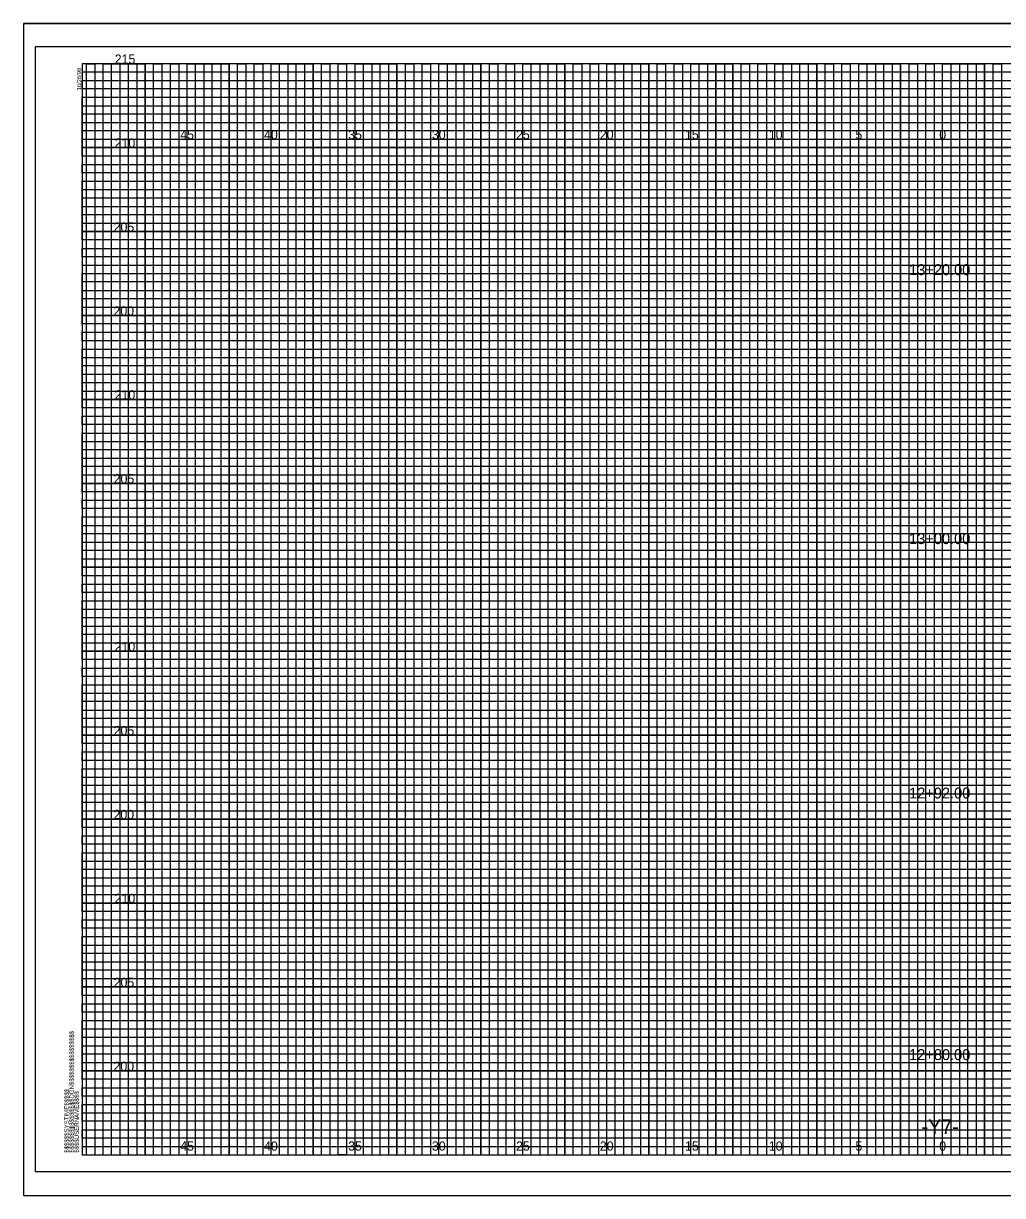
# Model space of a CAD drawing. Extents: x -4 to 103, y -2 to 351.
# Drawn here: x -3.5 to 54.8, y 210.1 to 279.9 of the extents above; entities that cross this region are included whole.
import ezdxf

# ---------------------------------------------------------------- set-up
doc = ezdxf.new("R2010")
doc.units = 0
for name, color, linetype in [('Exist XS Ground Line', 7, 'Continuous'), ('Old_Level_10', 7, 'Continuous'), ('Old_Level_16', 7, 'Continuous'), ('Old_Level_3', 7, 'Continuous'), ('Old_Level_4', 7, 'Continuous'), ('Old_Level_5', 7, 'Continuous'), ('Old_Level_6', 7, 'Continuous'), ('Old_Level_8', 7, 'Continuous'), ('Prop XS Finish Grade', 7, 'Continuous'), ('Prop XS SE Text', 7, 'Continuous'), ('Prop XS Subgrade Earthwork', 7, 'Continuous')]:
    doc.layers.add(name, color=color, linetype=linetype)

msp = doc.modelspace()

# ---------------------------------------------------------------- linework, layer by layer
at = {"layer": 'Old_Level_10'}
for p, q in [((1.25, 212.475), (1.25, 277.475)), ((3.75, 212.475), (3.75, 277.475)), ((6.25, 212.475), (6.25, 277.475)), ((8.75, 212.475), (8.75, 277.475)), ((11.25, 212.475), (11.25, 277.475)), ((13.75, 212.475), (13.75, 277.475)), ((16.25, 212.475), (16.25, 277.475)), ((18.75, 212.475), (18.75, 277.475)), ((21.25, 212.475), (21.25, 277.475)), ((23.75, 212.475), (23.75, 277.475)), ((26.25, 212.475), (26.25, 277.475)), ((28.75, 212.475), (28.75, 277.475)), ((31.25, 212.475), (31.25, 277.475)), ((33.75, 212.475), (33.75, 277.475)), ((36.25, 212.475), (36.25, 277.475)), ((38.75, 212.475), (38.75, 277.475)), ((41.25, 212.475), (41.25, 277.475)), ((43.75, 212.475), (43.75, 277.475)), ((46.25, 212.475), (46.25, 277.475)), ((48.75, 212.475), (48.75, 277.475)), ((51.25, 212.475), (51.25, 277.475)), ((53.75, 212.475), (53.75, 277.475)), ((0, 274.975), (74.25, 274.975)), ((0, 272.475), (102.5, 272.475)), ((0, 269.975), (102.5, 269.975)), ((0, 267.475), (102.5, 267.475)), ((0, 264.975), (102.5, 264.975)), ((0, 262.475), (102.5, 262.475)), ((0, 259.975), (102.5, 259.975)), ((0, 257.475), (102.5, 257.475)), ((0, 254.975), (102.5, 254.975)), ((0, 252.475), (102.5, 252.475)), ((0, 249.975), (102.5, 249.975)), ((0, 247.475), (102.5, 247.475)), ((0, 244.975), (102.5, 244.975)), ((0, 242.475), (102.5, 242.475)), ((0, 239.975), (102.5, 239.975)), ((0, 237.475), (102.5, 237.475)), ((0, 234.975), (102.5, 234.975)), ((0, 232.475), (102.5, 232.475)), ((0, 229.975), (102.5, 229.975)), ((0, 227.475), (102.5, 227.475)), ((0, 224.975), (102.5, 224.975)), ((0, 222.475), (102.5, 222.475)), ((0, 219.975), (102.5, 219.975)), ((0, 217.475), (102.5, 217.475)), ((0, 214.975), (102.5, 214.975))]:
    msp.add_line(p, q, dxfattribs=at)
at = {"layer": 'Old_Level_3'}
for p, q in [((-3.5, 279.875), (103.4, 279.875)), ((-3.5, 279.875), (-3.5, 210.05)), ((-3.5, 210.05), (102.1625, 210.05))]:
    msp.add_line(p, q, dxfattribs=at)
at = {"layer": 'Old_Level_4'}
for points in [[(0.25, 212.475), (0.25, 277.475), (0.75, 277.475), (0.75, 212.475), (1.75, 212.475), (1.75, 277.475), (2.25, 277.475), (2.25, 212.475), (2.75, 212.475), (2.75, 277.475), (3.25, 277.475), (3.25, 212.475), (4.25, 212.475), (4.25, 277.475), (4.75, 277.475), (4.75, 212.475), (5.25, 212.475), (5.25, 277.475), (5.75, 277.475), (5.75, 212.475), (6.75, 212.475), (6.75, 277.475), (7.25, 277.475), (7.25, 212.475), (7.75, 212.475), (7.75, 277.475), (8.25, 277.475), (8.25, 212.475), (9.25, 212.475), (9.25, 277.475), (9.75, 277.475), (9.75, 212.475), (10.25, 212.475), (10.25, 277.475), (10.75, 277.475), (10.75, 212.475), (11.75, 212.475), (11.75, 277.475), (12.25, 277.475), (12.25, 212.475), (12.75, 212.475), (12.75, 277.475), (13.25, 277.475), (13.25, 212.475), (14.25, 212.475), (14.25, 277.475), (14.75, 277.475), (14.75, 212.475), (15.75, 212.475), (15.25, 212.475), (15.25, 277.475), (15.75, 277.475), (15.75, 212.475), (16.75, 212.475), (16.75, 277.475), (17.25, 277.475), (17.25, 212.475), (17.75, 212.475), (17.75, 277.475), (18.25, 277.475), (18.25, 212.475), (19.25, 212.475), (19.25, 277.475), (19.75, 277.475), (19.75, 212.475), (20.25, 212.475), (20.25, 277.475), (20.75, 277.475), (20.75, 212.475), (21.75, 212.475), (21.75, 277.475), (22.25, 277.475), (22.25, 212.475), (22.75, 212.475), (22.75, 277.475), (23.25, 277.475), (23.25, 212.475), (24.25, 212.475), (24.25, 277.475), (24.75, 277.475), (24.75, 212.475), (25.25, 212.475), (25.25, 277.475), (25.75, 277.475), (25.75, 212.475), (26.75, 212.475), (26.75, 277.475), (27.25, 277.475), (27.25, 212.475), (27.75, 212.475), (27.75, 277.475), (28.25, 277.475), (28.25, 212.475), (29.25, 212.475), (29.25, 277.475), (29.75, 277.475), (29.75, 212.475), (30.25, 212.475), (30.25, 277.475), (30.75, 277.475), (30.75, 212.475)], [(30.75, 212.475), (31.75, 212.475), (31.75, 277.475), (32.25, 277.475), (32.25, 212.475), (32.75, 212.475), (32.75, 277.475), (33.25, 277.475), (33.25, 212.475), (34.25, 212.475), (34.25, 277.475), (34.75, 277.475), (34.75, 212.475), (35.25, 212.475), (35.25, 277.475), (35.75, 277.475), (35.75, 212.475), (36.75, 212.475), (36.75, 277.475), (37.25, 277.475), (37.25, 212.475), (37.75, 212.475), (37.75, 277.475), (37.75, 212.475)], [(38.25, 277.475), (38.25, 212.475), (39.25, 212.475), (39.25, 277.475), (39.75, 277.475), (39.75, 212.475), (40.25, 212.475), (40.25, 277.475), (40.75, 277.475), (40.75, 212.475), (41.75, 212.475), (41.75, 277.475), (42.25, 277.475), (42.25, 212.475), (42.75, 212.475), (42.75, 277.475), (43.25, 277.475), (43.25, 212.475), (43.75, 212.475), (44.25, 212.475), (44.25, 277.475), (44.75, 277.475), (44.75, 212.475), (45.25, 212.475), (45.25, 277.475), (45.75, 277.475), (45.75, 212.475), (46.75, 212.475), (46.75, 277.475), (47.25, 277.475), (47.25, 212.475), (47.75, 212.475), (47.75, 277.475), (48.25, 277.475), (48.25, 212.475), (49.25, 212.475), (49.25, 277.475), (49.75, 277.475), (49.75, 212.475), (50.25, 212.475), (50.25, 277.475), (50.75, 277.475), (50.75, 212.475), (51.75, 212.475), (51.75, 277.475), (52.25, 277.475), (52.25, 212.475), (52.75, 212.475), (52.75, 277.475), (53.25, 277.475), (53.25, 212.475), (54.25, 212.475), (54.25, 277.475), (54.75, 277.475), (54.75, 212.475), (55.25, 212.475)], [(0, 274.475), (0, 275.475), (74.25, 275.475), (74.25, 275.975), (0, 275.975), (0, 276.475), (74.25, 276.475), (74.25, 276.975), (0, 276.975)], [(102.5, 274.475), (0, 274.475)], [(102.5, 273.475), (0, 273.475), (0, 273.975), (102.5, 273.975)], [(102.5, 271.975), (0, 271.975), (0, 272.975), (102.5, 272.975)], [(102.5, 270.975), (0, 270.975), (0, 271.475), (102.5, 271.475)], [(102.5, 269.475), (0, 269.475), (0, 270.475), (102.5, 270.475)], [(102.5, 268.475), (0, 268.475), (0, 268.975), (102.5, 268.975)], [(102.5, 266.975), (0, 266.975), (0, 267.975), (102.5, 267.975)], [(102.5, 265.975), (0, 265.975), (0, 266.475), (102.5, 266.475)], [(0, 265.475), (102.5, 265.475)], [(102.5, 264.475), (0, 264.475)], [(102.5, 263.475), (0, 263.475), (0, 263.975), (102.5, 263.975)], [(102.5, 261.975), (0, 261.975), (0, 262.975), (102.5, 262.975)], [(102.5, 260.975), (0, 260.975), (0, 261.475), (102.5, 261.475)], [(102.5, 259.475), (0, 259.475), (0, 260.475), (102.5, 260.475)], [(102.5, 258.475), (0, 258.475), (0, 258.975), (102.5, 258.975)], [(102.5, 256.975), (0, 256.975), (0, 257.975), (102.5, 257.975)], [(102.5, 255.975), (0, 255.975), (0, 256.475), (102.5, 256.475)], [(102.5, 254.475), (0, 254.475), (0, 255.475), (102.5, 255.475)], [(102.5, 253.475), (0, 253.475), (0, 253.975), (102.5, 253.975)], [(102.5, 251.975), (0, 251.975), (0, 252.975), (102.5, 252.975)], [(102.5, 250.975), (0, 250.975), (0, 251.475), (102.5, 251.475)], [(102.5, 249.475), (0, 249.475), (0, 250.475), (102.5, 250.475)], [(102.5, 248.475), (0, 248.475), (0, 248.975), (102.5, 248.975)], [(102.5, 246.975), (0, 246.975), (0, 247.975), (102.5, 247.975)], [(102.5, 245.975), (0, 245.975), (0, 246.475), (102.5, 246.475)], [(102.5, 244.475), (0, 244.475), (0, 245.475), (102.5, 245.475)], [(102.5, 243.475), (0, 243.475), (0, 243.975)], [(0, 243.975), (102.5, 243.975)], [(102.5, 241.975), (0, 241.975), (0, 242.975), (102.5, 242.975)], [(102.5, 240.975), (0, 240.975), (0, 241.475), (102.5, 241.475)], [(102.5, 239.475), (0, 239.475), (0, 240.475), (102.5, 240.475)], [(102.5, 238.475), (0, 238.475), (0, 238.975), (102.5, 238.975)], [(102.5, 236.975), (0, 236.975), (0, 237.975), (102.5, 237.975)], [(102.5, 235.975), (0, 235.975), (0, 236.475), (102.5, 236.475)], [(102.5, 234.475), (0, 234.475), (0, 235.475), (102.5, 235.475)], [(102.5, 233.475), (0, 233.475), (0, 233.975), (102.5, 233.975)], [(102.5, 231.975), (0, 231.975), (0, 232.975), (102.5, 232.975)], [(102.5, 230.975), (0, 230.975), (0, 231.475), (102.5, 231.475)], [(102.5, 229.475), (0, 229.475), (0, 230.475), (102.5, 230.475)], [(102.5, 228.475), (0, 228.475), (0, 228.975), (102.5, 228.975)], [(102.5, 226.975), (0, 226.975), (0, 227.975), (102.5, 227.975)], [(102.5, 225.975), (0, 225.975), (0, 226.475), (102.5, 226.475)], [(102.5, 224.475), (0, 224.475), (0, 225.475), (102.5, 225.475)], [(102.5, 223.475), (0, 223.475), (0, 223.975), (102.5, 223.975)], [(102.5, 221.975), (0, 221.975), (0, 222.975), (102.5, 222.975)], [(102.5, 220.975), (0, 220.975), (0, 221.475), (102.5, 221.475)], [(102.5, 219.475), (0, 219.475), (0, 220.475), (102.5, 220.475)], [(102.5, 218.475), (0, 218.475), (0, 218.975), (102.5, 218.975)], [(102.5, 216.975), (0, 216.975), (0, 217.975), (102.5, 217.975)], [(102.5, 215.975), (0, 215.975), (0, 216.475), (102.5, 216.475)], [(102.5, 214.475), (0, 214.475), (0, 215.475), (102.5, 215.475)], [(102.5, 213.475), (0, 213.475), (0, 213.975), (102.5, 213.975)], [(0, 212.975), (102.5, 212.975)]]:
    msp.add_lwpolyline(points, dxfattribs=at)
at = {"layer": 'Old_Level_5'}
msp.add_lwpolyline([(103.4, 279.875), (-3.5, 279.875), (-3.5, 210.05), (103.4, 210.05)], close=True, dxfattribs=at)
at = {"layer": 'Old_Level_6'}
for p, q in [((0, 212.475), (0, 212.475)), ((0, 212.475), (0, 212.475)), ((-3.5, 210.05), (103.4, 210.05))]:
    msp.add_line(p, q, dxfattribs=at)
msp.add_lwpolyline([(102.5, 277.475), (0, 277.475), (0, 212.475), (102.5, 212.475)], close=True, dxfattribs=at)
at = {"layer": 'Old_Level_8'}
for points in [[(1.25, 212.475), (1.25, 277.475), (3.75, 277.475), (3.75, 212.475), (6.25, 212.475), (6.25, 277.475), (8.75, 277.475), (8.75, 212.475), (11.25, 212.475), (11.25, 277.475), (13.75, 277.475), (13.75, 212.475), (16.25, 212.475), (16.25, 277.475), (18.75, 277.475), (18.75, 212.475), (21.25, 212.475), (21.25, 277.475), (23.75, 277.475), (23.75, 212.475), (26.25, 212.475), (26.25, 277.475), (28.75, 277.475), (28.75, 212.475), (31.25, 212.475), (31.25, 277.475), (33.75, 277.475), (33.75, 212.475), (36.25, 212.475), (36.25, 277.475), (38.75, 277.475), (38.75, 212.475), (41.25, 212.475), (41.25, 277.475), (43.75, 277.475), (43.75, 212.475), (46.25, 212.475), (46.25, 277.475), (48.75, 277.475), (48.75, 212.475), (51.25, 212.475), (51.25, 277.475), (53.75, 277.475), (53.75, 212.475)], [(102.5, 272.475), (0, 272.475), (0, 274.975), (74.25, 274.975)], [(102.5, 267.475), (0, 267.475), (0, 269.975), (102.5, 269.975)], [(102.5, 262.475), (0, 262.475), (0, 264.975), (102.5, 264.975)], [(102.5, 257.475), (0, 257.475), (0, 259.975), (102.5, 259.975)], [(102.5, 252.475), (0, 252.475), (0, 254.975), (102.5, 254.975)], [(102.5, 247.475), (0, 247.475), (0, 249.975), (102.5, 249.975)], [(102.5, 242.475), (0, 242.475), (0, 244.975), (102.5, 244.975)], [(102.5, 237.475), (0, 237.475), (0, 239.975), (102.5, 239.975)], [(102.5, 232.475), (0, 232.475), (0, 234.975), (102.5, 234.975)], [(102.5, 227.475), (0, 227.475), (0, 229.975), (102.5, 229.975)], [(102.5, 222.475), (0, 222.475), (0, 224.975), (102.5, 224.975)], [(102.5, 217.475), (0, 217.475), (0, 219.975), (102.5, 219.975)], [(0, 214.975), (102.5, 214.975)]]:
    msp.add_lwpolyline(points, dxfattribs=at)
at = {"layer": 'Prop XS SE Text'}
msp.add_lwpolyline([(103, 278.475), (-2.8, 278.475), (-2.8, 211.475), (103, 211.475)], close=True, dxfattribs=at)

# ---------------------------------------------------------------- texts
at = {"layer": 'Exist XS Ground Line'}
msp.add_text('-Y7-', height=0.875, dxfattribs=at).set_placement((49.9985, 213.725))
at = {"layer": 'Old_Level_16'}
for s, p in [('45', (5.8399, 272.975)), ('40', (10.8313, 272.975)), ('35', (15.8399, 272.975)), ('30', (20.8313, 272.975)), ('25', (25.8399, 272.975)), ('20', (30.8313, 272.975)), ('15', (35.9058, 272.975)), ('10', (40.8971, 272.975)), ('5', (46.0574, 272.975)), ('0', (51.0488, 272.975)), ('0', (51.0488, 272.975)), ('45', (5.8399, 212.725)), ('40', (10.8313, 212.725)), ('35', (15.8399, 212.725)), ('30', (20.8313, 212.725)), ('25', (25.8399, 212.725)), ('20', (30.8313, 212.725)), ('15', (35.9058, 212.725)), ('10', (40.8971, 212.725)), ('5', (46.0574, 212.725)), ('0', (51.0488, 212.725)), ('0', (51.0488, 212.725))]:
    msp.add_text(s, height=0.55, dxfattribs=at).set_placement(p)
at = {"layer": 'Old_Level_6'}
for s, height, p in [('10/26/98', 0.25, (-0.0625, 275.8845)), ('$$$$$$$$$$$$$$$$DGN$$$$$$$$$$$$$$$$', 0.2625, (-0.5, 212.6)), ('$$$$$$SYSTIME$$$$$', 0.2625, (-0.7973, 212.5997)), ('$$$$USERNAME$$$$', 0.2625, (-0.2, 212.6))]:
    msp.add_text(s, height=height, rotation=90, dxfattribs=at).set_placement(p)
at = {"layer": 'Old_Level_8'}
msp.add_text('040397', height=0.0025, rotation=90, dxfattribs=at).set_placement((-0.0007, 277.4614))
at = {"layer": 'Prop XS Finish Grade'}
for s, p in [('215', (1.9383, 277.475)), ('210', (1.9296, 272.475)), ('205', (1.8724, 267.475)), ('200', (1.8638, 262.475)), ('210', (1.9296, 257.475)), ('205', (1.8724, 252.475)), ('210', (1.9296, 242.475)), ('205', (1.8724, 237.475)), ('200', (1.8638, 232.475)), ('210', (1.9296, 227.475)), ('205', (1.8724, 222.475)), ('200', (1.8638, 217.475))]:
    msp.add_text(s, height=0.55, dxfattribs=at).set_placement(p)
at = {"layer": 'Prop XS Subgrade Earthwork'}
for s, p in [('13+20.00', (49.2508, 264.8811)), ('13+00.00', (49.2508, 248.8597)), ('12+92.00', (49.2508, 233.7041)), ('12+80.00', (49.2508, 218.1218))]:
    msp.add_text(s, height=0.65, dxfattribs=at).set_placement(p)

doc.saveas('drawing.dxf')
